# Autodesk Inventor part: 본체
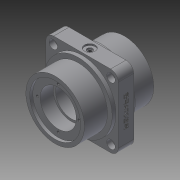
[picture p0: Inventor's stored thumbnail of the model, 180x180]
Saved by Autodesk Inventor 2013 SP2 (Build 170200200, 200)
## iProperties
Created: 2023-10
Part Number: 본체
Material: Generic
Document SubType Name: Modeling
Designer: i
Density: 1 g/cm^3
Author: i
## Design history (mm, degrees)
sketch "스케치1"
  geometry: L1 (-45, 0)-(45, 0); L2 (-45, 0)-(-45, 38); L3 (45, 38)-(45, 0); L4 (-45, 38)-(-15, 38); L5 (-15, 38)-(-15, 44); L6 (-15, 44)-(15, 44); L7 (15, 44)-(15, 38); L8 (15, 38)-(45, 38); 3 further points
  constraints: 16 end point, 4 horizontal, 4 vertical, 2 midpoint, 1 coincident, 1 vertical alignment
  dimensions: "d0" = 90 distance of L1.start L1.end; "d4" = 76 diameter of L4 L1; "d5" = 88 diameter of L6 L1; "d6" = 76 diameter of L8 L1; "d7" = 30 distance of L5.end L6.end
revolve "회전1" sketch "스케치1" stored, may be unused: angle "d3" = 90 deg
sketch "스케치2" dims "d47" = 27
  geometry: L1 (-45, -38)-(-45, 38) reference; L2 (45, -38)-(45, 38) reference; L3 (-45, 0)-(45, 0); L4 (-45, 0)-(-45, 33); L5 (-41, 33)-(-41, 23.5); L6 (-41, 23.5)-(-24, 23.5); L7 (-24, 23.5)-(-24, 20.5); L8 (-24, 20.5)-(24, 20.5); L9 (24, 20.5)-(24, 23.5); L10 (24, 23.5)-(41, 23.5); L11 (41, 23.5)-(41, 33); L12 (41, 33)-(45, 33); L13 (-41, 33)-(-45, 33); 1 further point
  constraints: 22 end point, 5 horizontal, 4 vertical, 2 midpoint, 2 point on line
  dimensions: "d8" = 66 diameter of L13 L3; "d10" = 47 diameter of L6 L3; "d11" = 41 diameter of L8 L3; "d13" = 47 diameter of L10 L3; "d14" = 66 diameter of L12 L3; "d15" = 4 distance of L5.start L4.end; "d16" = 17 distance of L5.end L6.end; "d17" = 4 distance of L11.end L12.end; "d18" = 17 distance of L9.end L10.end
revolve "회전2" sketch "스케치2" stored, may be unused: angle "d19" = 90 deg
sketch "스케치3"
  geometry: L1 (-47, 47)-(47, 47); L2 (47, 47)-(47, -47); L3 (47, -47)-(-47, -47); L4 (-47, -47)-(-47, 47); L5 (-47, 47)-(47, -47); L6 (47, 47)-(-47, -47); C1 r 44 at (0, 0) reference; C2 r 44 at (0, 0); 1 further point
  constraints: 12 end point, 2 midpoint, 2 parallel, 1 centre point, 1 coincident, 1 concentric, 1 horizontal, 1 perpendicular
  dimensions: "d20" = 94 distance of L1.end L2.end; "d22" = 94 distance of L2.end L3.end
extrude "돌출1" join sketch "스케치3" stored distance "d23" = 20; taper "d24" = 0 deg
fillet "모깎기1" dims "d25" = 10
sketch "스케치4"
  geometry: 2 further points
  constraints: 1 coincident
hole "구멍1" sketch "스케치4" at (10, -37) diameter "d26" = 14; stored, may be unused: countersink angle "d30" = 90 deg, drill point angle "d32" = 0 deg; dims "d27" = 6, "d28" = 4, "d29" = 2, "d31" = 2
sketch "스케치9"
  geometry: L1 (0, 0)-(37.477, 37.477); L2 (0, 0)-(53, 0); C1 r 3.3 at (37.477, 37.477)
  constraints: 4 end point, 1 centre point, 1 coincident, 1 equal length, 1 horizontal
  dimensions: "d33" = 53 distance of L1.start L1.end; "d34" = 45 deg angle of L2 L1; "d35" = 6.6 diameter of C1
extrude "돌출2" cut sketch "스케치9" stored distance "d36" = 20; taper "d37" = 0 deg
sketch "스케치10"
  geometry: C1 r 3.3 at (-37.477, 37.477) reference; C2 r 3.3 at (-37.477, -37.477) reference; C3 r 3.3 at (37.477, -37.477) reference; C4 r 3.3 at (37.477, 37.477) reference; C5 r 5.5 at (-37.477, 37.477)
  constraints: 1 centre point, 1 coincident
  dimensions: "d41" = 11 diameter of C5
extrude "돌출3" cut sketch "스케치10" distance "d42" = 7; taper "d43" = 0 deg
sketch "스케치11"
  geometry: L1 (0, 0)-(0, 27); C1 r 33 at (0, 0) reference
  constraints: 2 end point, 1 vertical
  dimensions: "d47" = 27 distance of L1.start L1.end
hole "구멍2" sketch "스케치11" at (0, 27) diameter "d48" = 3.242; stored, may be unused: countersink angle "d52" = 90 deg, drill point angle "d54" = 118 deg; dims "d49" = 8, "d50" = 7, "d51" = 2, "d53" = 10
sketch "스케치12"
  geometry: L1 (0, 0)-(0, 27); C1 r 23.5 at (0, 0) reference
  constraints: 2 end point, 1 vertical
  dimensions: "d55" = 27 distance of L1.start L1.end
hole "구멍3" sketch "스케치12" at (0, 27) diameter "d56" = 3.242; stored, may be unused: countersink angle "d60" = 90 deg, drill point angle "d62" = 118 deg; dims "d57" = 8, "d58" = 7, "d59" = 2, "d61" = 10
sketch "스케치13"
  geometry: C1 r 7 at (0, 0) reference; C2 r 3.5 at (0, 0)
  constraints: 1 centre point, 1 coincident
  dimensions: "d66" = 7 diameter of C2
extrude "돌출4" cut sketch "스케치13" distance "d67" = 2; taper "d68" = 0 deg
hole "구멍4" diameter "d71" = 5.188; stored, may be unused: countersink angle "d75" = 90 deg, drill point angle "d77" = 118 deg; dims "d69" = 10, "d70" = 10, "d72" = 12, "d73" = 7, "d74" = 2, "d76" = 10
sketch "스케치14"
  geometry: L1 (0, 74)-(0, 84) reference; 2 further points
  constraints: 2 coincident, 1 other
  dimensions: "d78" = 10 distance from line of point (10, 37) L1 (derived)
feature "엠보싱1" sketch "스케치14" dims "d0" = 90, "d4" = 76, "d5" = 88, "d6" = 76, "d7" = 30, "d79" = 0.5, "d80" = 0
node "솔리드1"
pattern_circular "원형 패턴1" dims angle "d39" = 360 deg
mirror "대칭1"
pattern_circular "원형 패턴2" dims angle "d45" = 360 deg
pattern_circular "원형 패턴3" dims angle "d64" = 360 deg
